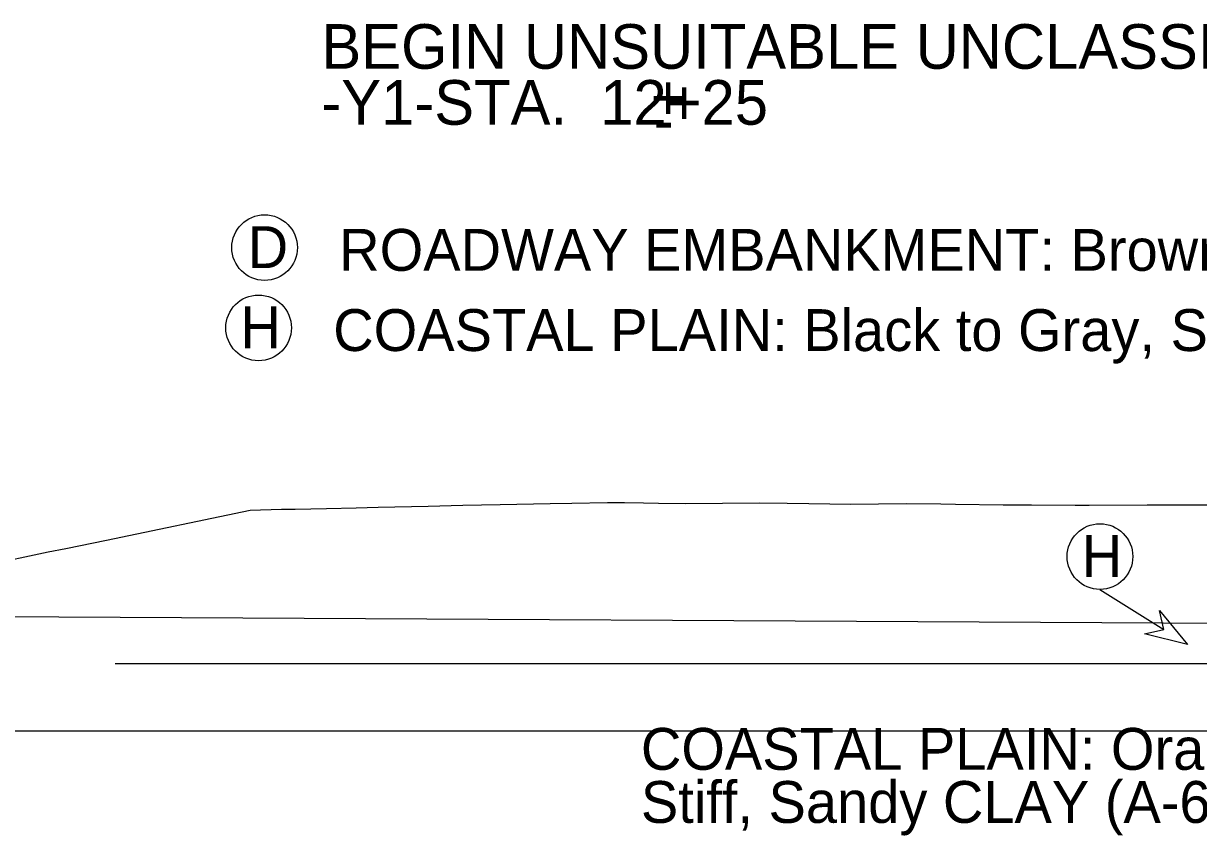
# Model space of a CAD drawing. Extents: x -516 to 303, y -10 to 5017.
# Drawn here: x 97.61 to 139.69, y 1996.25 to 2025.35 of the extents above; entities that cross this region are included whole.
import ezdxf

# ---------------------------------------------------------------- set-up
doc = ezdxf.new("R2010")
doc.units = 0
for name, color, linetype in [('Exist Cross Section Cell', 7, 'Continuous'), ('Exist XS Ground Line', 7, 'Continuous'), ('Misc Plan Tools Cell', 7, 'Continuous'), ('Prop Road Sect_ Material - Bubble + Leader + Bubble Tx', 7, 'Continuous'), ('Prop Road Sect_ Material - Contact (General - Major)', 7, 'Continuous'), ('Prop Road Sect_ Material - Contact (General - Minor)', 7, 'Continuous'), ('Prop Road Sect_ Material - Tx (Composite Desc)', 7, 'Continuous'), ('Prop Road Sect_ Recs - UUC (Tx)', 7, 'Continuous')]:
    doc.layers.add(name, color=color, linetype=linetype)

msp = doc.modelspace()

# ---------------------------------------------------------------- linework, layer by layer
at = {"layer": 'Exist Cross Section Cell'}
msp.add_line((0, 2000), (150, 2000), dxfattribs=at)
at = {"layer": 'Exist XS Ground Line'}
msp.add_lwpolyline([(96.244, 2005.939), (98.493, 2006.413), (99.129, 2006.531), (100.579, 2006.836), (105.726, 2007.905), (106.85, 2007.938), (107.344, 2007.943), (108.465, 2007.971), (109.527, 2007.993), (110.313, 2008.012), (112.102, 2008.054), (113.346, 2008.083), (114.684, 2008.114), (116.466, 2008.147), (117.246, 2008.161), (118.521, 2008.178), (118.831, 2008.182), (119.137, 2008.177), (119.815, 2008.165), (120.344, 2008.159), (121.305, 2008.148), (122.644, 2008.162), (123.979, 2008.174), (124.961, 2008.158), (125.731, 2008.145), (127.233, 2008.12), (129.216, 2008.146), (130.459, 2008.129), (130.982, 2008.124), (132.688, 2008.104), (133.709, 2008.095), (135.269, 2008.084), (135.77, 2008.086), (137.85, 2008.093), (139.074, 2008.1), (140.417, 2008.103)], dxfattribs=at)
at = {"layer": 'Misc Plan Tools Cell'}
msp.add_lwpolyline([(138.292, 2004.316), (139.294, 2003.093), (137.758, 2003.47), (138.448, 2003.627)], close=True, dxfattribs=at)
at = {"layer": 'Prop Road Sect_ Material - Bubble + Leader + Bubble Tx'}
msp.add_line((136.16, 2005.07), (138.448, 2003.627), dxfattribs=at)
for centre in [(106.244, 2017.315), (106.029, 2014.44), (136.16, 2006.245)]:
    msp.add_circle(centre, 1.176, dxfattribs=at)
at = {"layer": 'Prop Road Sect_ Material - Contact (General - Major)'}
msp.add_line((33.373, 2004.451), (189.047, 2003.593), dxfattribs=at)
at = {"layer": 'Prop Road Sect_ Material - Contact (General - Minor)'}
msp.add_line((100.895, 2002.408), (199.105, 2002.408), dxfattribs=at)

# ---------------------------------------------------------------- texts
at = {"layer": 'Prop Road Sect_ Material - Tx (Composite Desc)'}
for s, p in [('D', (105.638, 2016.583)), ('ROADWAY EMBANKMENT: Brown, Medium Stiff to Stiff, Silty CLAY (A-7-6), Highly Plastic, Moist', (108.916, 2016.484)), ('H', (105.376, 2013.709)), ('COASTAL PLAIN: Black to Gray, Stiff, Sandy SILT (A-4), Moist (Black Creek Formation)', (108.701, 2013.61)), ('H', (135.508, 2005.514)), ('COASTAL PLAIN: Orange-Brown and Gray, Soft to Medium ', (119.72, 1998.603)), ('Stiff, Sandy CLAY (A-6), Moist to Wet (Black Creek Formation)', (119.72, 1996.701))]:
    msp.add_text(s, height=1.5, dxfattribs=at).set_placement(p)
at = {"layer": 'Prop Road Sect_ Recs - UUC (Tx)'}
for s, p in [('BEGIN UNSUITABLE UNCLASSIFIED EXCAVATION-MATERIAL TO BE WASTED', (108.277, 2023.723)), ('-Y1-STA.  12+25', (108.277, 2021.719)), ('+', (120.069, 2021.893)), ('-', (120.176, 2021.088))]:
    msp.add_text(s, height=1.6, dxfattribs=at).set_placement(p)

doc.saveas('drawing.dxf')
